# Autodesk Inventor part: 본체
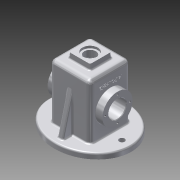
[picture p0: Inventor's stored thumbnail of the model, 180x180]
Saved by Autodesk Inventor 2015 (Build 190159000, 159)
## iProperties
Created: 2017-07
Part Number: 본체
Material: 알루미늄 6061
Document SubType Name: Modeling
Designer: Administrator
Density: 2.7 g/cm^3
Appearance: 알루미늄 - 평지
Mass: 889.257 g
Surface Area: 988.087 cm^2
Volume: 329.355 cm^3
Author: Administrator
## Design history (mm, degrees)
sketch "스케치1"
  geometry: L1 (-37, 37)-(37, 37); L2 (37, 37)-(37, -37); L3 (37, -37)-(-37, -37); L4 (-37, -37)-(-37, 37); L5 (-37, 37)-(37, -37); 2 further points
  constraints: 10 end point, 2 parallel, 1 coincident, 1 horizontal, 1 midpoint, 1 perpendicular
  dimensions: "d3" = 74 distance of L2.end L3.end; "d4" = 74 distance of L1.end L2.end
extrude "돌출1" new body sketch "스케치1" distance "d5" = 110; taper "d6" = 0 deg
sketch "스케치2"
  geometry: 2 further points; 1 other entity
  constraints: 1 coincident, 2 other
extrude "돌출2" join sketch "스케치2" distance "d7" = 10; taper "d8" = 0 deg
sketch "스케치3"
  geometry: L1 (-37, -37)-(37, -37) reference; L2 (37, -37)-(37, 37) reference; L3 (37, 37)-(-37, 37) reference; L4 (-37, 37)-(-37, -37) reference; L5 (-20, 20)-(20, 20); L6 (20, 20)-(20, -20); L7 (20, -20)-(-20, -20); L8 (-20, -20)-(-20, 20); L9 (-20, 20)-(20, -20); 2 further points
  constraints: 10 end point, 2 parallel, 1 coincident, 1 horizontal, 1 midpoint, 1 perpendicular
  dimensions: "d9" = 40 distance of L5.end L6.end; "d10" = 40 distance of L5.start L5.end
extrude "돌출3" join sketch "스케치3" distance "d11" = 10; taper "d12" = -5 deg
sketch "스케치4"
  geometry: C1 r 14 at (0, 0); 1 further point
  constraints: 1 centre point, 1 coincident
  dimensions: "d13" = 28 diameter of C1
extrude "돌출4" cut sketch "스케치4" distance "d14" = 4; taper "d15" = 0 deg
sketch "스케치5"
  geometry: C1 r 10.5 at (0, 0); 1 further point
  constraints: 1 centre point, 1 coincident
  dimensions: "d16" = 21 diameter of C1
extrude "돌출5" cut sketch "스케치5" stored distance "d17" = 4; taper "d18" = 0 deg
fillet "모깎기1" dims "d19" = 8
node "작업 평면1"
sketch "스케치6"
  geometry: L1 (-94, -10)-(36, -10) reference; C1 r 27.5 at (-29, 45); 1 further point
  constraints: 1 centre point, 1 vertical alignment
  dimensions: "d21" = 55 diameter of C1; "d22" = 55 distance from line of L1 C1.centre
extrude "돌출6" join sketch "스케치6" distance "d23" = 100; taper "d24" = 0 deg
sketch "스케치7"
  geometry: C1 r 27.5 at (0, 0) reference; C2 r 16 at (0, 0); 1 further point
  constraints: 1 centre point, 1 coincident
  dimensions: "d25" = 32 diameter of C2
extrude "돌출7" cut sketch "스케치7" stored distance "d26" = 100; taper "d27" = 0 deg
chamfer "모따기1" distance "d28" = 1; stored, may be unused: second distance "d29" = 2, angle "d30" = 45 deg
chamfer "모따기2" distance "d31" = 1; stored, may be unused: second distance "d32" = 2, angle "d33" = 45 deg
sketch "스케치8"
  geometry: L1 (-32, 32)-(32, 32); L2 (32, 32)-(32, -32); L3 (32, -32)-(-32, -32); L4 (-32, -32)-(-32, 32); L5 (-32, 32)-(32, -32); 2 further points
  constraints: 10 end point, 2 parallel, 1 coincident, 1 horizontal, 1 midpoint, 1 perpendicular
  dimensions: "d34" = 64 distance of L1.start L1.end; "d35" = 64 distance of L1.end L2.end
extrude "돌출8" cut sketch "스케치8" distance "d36" = 105; taper "d37" = 0 deg
sketch "스케치9"
  geometry: L1 (-32, 39)-(-49, 39) reference; L2 (-32, 71)-(-49, 71) reference; L3 (-47.682, 55)-(53.416, 55); L4 (-32, 0)-(-32, 105) reference; L5 (-32, 82.5)-(-25, 75.5); L6 (-25, 75.5)-(-25, 71); L7 (-32, 71)-(-25, 71); 1 further point
  constraints: 8 end point, 2 perpendicular, 1 horizontal, 1 point on line
  dimensions: "d38" = 7 distance between parallel lines of L4 L6; "d39" = 135 deg angle of L4 L5; "d40" = 55 diameter of L5.start L3; "d41" = 32 diameter of L1 L3
revolve "회전1" sketch "스케치9" stored, may be unused: angle "d42" = 90 deg
fillet "모깎기2" dims "d43" = 0.5
fillet "모깎기3" dims "d44" = 0.5
fillet "모깎기4" dims "d45" = 0.5
fillet "모깎기5" dims "d46" = 3
fillet "모깎기6" dims "d47" = 3
fillet "모깎기7" dims "d48" = 3
fillet "모깎기8" dims "d49" = 3
fillet "모깎기9" dims "d50" = 3
sketch "스케치10"
  geometry: L1 (102, 32)-(0, 32) reference; L2 (0, 32)-(0, 65) reference; L3 (0, 65)-(7, 65) reference; L4 (10, 62)-(10, 37) reference; L5 (10, 37)-(102, 37) reference; L6 (110, 29)-(110, 22.749) reference; L7 (112.739, 19.76)-(120, 19.125) reference; L8 (120, 19.125)-(120, 14) reference; L9 (120, 14)-(116, 14) reference; L10 (116, 14)-(116, 10.5) reference; L11 (116, 10.5)-(105, 10.5) reference; L12 (105, 10.5)-(105, 29) reference; L13 (105, -29)-(105, -10.5) reference; L14 (105, -10.5)-(116, -10.5) reference; L15 (116, -10.5)-(116, -14) reference; L16 (116, -14)-(120, -14) reference; L17 (120, -14)-(120, -19.125) reference; L18 (120, -19.125)-(112.739, -19.76) reference; L19 (110, -22.749)-(110, -29) reference; L20 (102, -37)-(10, -37) reference; L21 (10, -37)-(10, -62) reference; L22 (7, -65)-(0, -65) reference; L23 (0, -65)-(0, -32) reference; L24 (0, -32)-(102, -32) reference; L25 (10, 55)-(82.194, 37); L26 (0, 0)-(105, 0); L27 (105, -29)-(105, 29) reference; L28 (10, -55)-(82.194, -37); L29 (10, -55)-(10, -37); L30 (0, 65)-(0, -65) reference; L31 (10, -37)-(82.194, -37); L32 (102, -37)-(10, -37) reference; A1 r 3 centre (102, 29) between (105, 29) and (102, 32) reference; A2 r 8 centre (102, 29) between (110, 29) and (102, 37) reference; A3 r 3 centre (113, 22.749) between (110, 22.749) and (112.739, 19.76) reference; A4 r 3 centre (102, -29) between (102, -32) and (105, -29) reference; A5 r 3 centre (113, -22.749) between (112.739, -19.76) and (110, -22.749) reference; A6 r 8 centre (102, -29) between (102, -37) and (110, -29) reference
  constraints: 10 end point, 2 point on line, 2 symmetric about line, 1 collinear, 1 midpoint, 1 parallel, 2 other
  dimensions: "d51" = 10 distance from line of L3 L25.start; "d52" = 14 deg angle of L3 L25
extrude "돌출9" join sketch "스케치10" stored distance "d53" = 10; taper "d54" = 0 deg
fillet "모깎기10" dims "d55" = 3
fillet "모깎기11" dims "d56" = 3
fillet "모깎기12" dims "d57" = 3
sketch "스케치11" dims "d58" = 45
  geometry: C1 r 27.5 at (0, 0) reference; C2 r 17 at (0, 0) reference; 3 further points
  constraints: 1 coincident, 1 vertical alignment, 2 other
hole "구멍1" sketch "스케치11" at (0, 22.5) diameter "d59" = 3.242; stored, may be unused: countersink angle "d63" = 90 deg, drill point angle "d65" = 118 deg; dims "d60" = 8, "d61" = 4, "d62" = 2, "d64" = 11.8
sketch "스케치12" dims "d69" = 45
  geometry: C1 r 27.5 at (0, 0) reference; C2 r 17 at (0, 0) reference; 3 further points
  constraints: 1 coincident, 1 vertical alignment, 2 other
hole "구멍2" sketch "스케치12" at (0, 22.5) diameter "d70" = 3.242; stored, may be unused: countersink angle "d74" = 90 deg, drill point angle "d76" = 118 deg; dims "d71" = 8, "d72" = 4, "d73" = 2, "d75" = 10
sketch "스케치13"
  geometry: L1 (0, 0)-(-91.036, 0); 1 further point
  constraints: 2 end point, 1 horizontal, 1 point on line
  dimensions: "d80" = 58 distance of point (-58, 0) L1.start
hole "구멍3" sketch "스케치13" at (-58, 0) diameter "d81" = 10; stored, may be unused: countersink angle "d85" = 90 deg, drill point angle "d87" = 118 deg; dims "d82" = 8, "d83" = 4, "d84" = 2, "d86" = 10
sketch "스케치14"
  geometry: L1 (8.261, -8.998)-(49.739, -8.998); L2 (49.739, -8.998)-(49.739, -15.002); L3 (49.739, -15.002)-(8.261, -15.002); L4 (8.261, -15.002)-(8.261, -8.998); L5 (8.261, -15.002)-(49.739, -8.998); L6 (8.261, -8.998)-(49.739, -15.002); L7 (45.137, 18)-(12.863, 18) reference; L8 (66, -89)-(66, 0) reference; 2 further points
  constraints: 4 end point, 1 midpoint, 2 other
  dimensions: "d91" = 30 distance from line of L7 point (29, -12); "d92" = 37 distance from line of L8 point (29, -12)
extrude "돌출10" join sketch "스케치14" distance "d93" = 0.5; taper "d94" = 0 deg
node "솔리드1"
mirror "대칭1"
pattern_circular "원형 패턴1" dims angle "d67" = 360 deg
pattern_circular "원형 패턴2" dims angle "d78" = 360 deg
pattern_linear "직사각형 패턴1" dims "d90" = 116
node "투영된 루프1"
node "투영된 루프2"
node "투영된 루프3"
node "투영된 루프4"
node "절단 모서리 투영1"
other parameters: "d20" = 13
